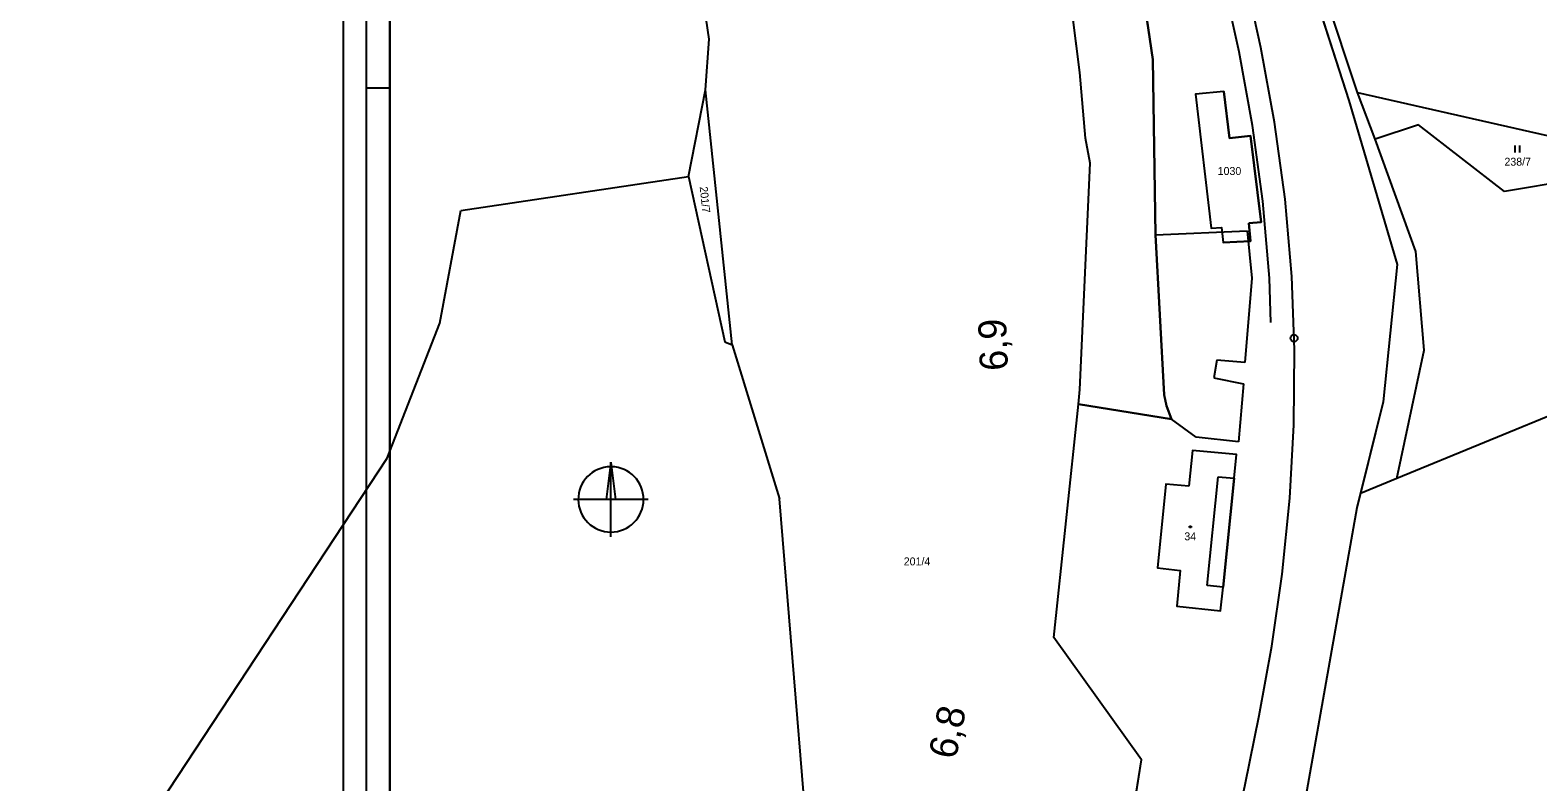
# Model space of a CAD drawing. Extents: x -866656 to -858817, y -1041816 to -1038653.
# Drawn here: x -864363.3 to -864040.4, y -1040809.9 to -1040648.8 of the extents above; entities that cross this region are included whole.
import ezdxf

# ---------------------------------------------------------------- set-up
doc = ezdxf.new("R2010")
doc.units = 0
for name, color, linetype in [('SZDC', 7, 'Continuous'), ('tisk ramy', 7, 'Continuous'), ('Vrstva 1', 7, 'Continuous'), ('Vrstva 2', 7, 'Continuous'), ('Vrstva 53', 7, 'Continuous'), ('Vrstva 7', 7, 'Continuous')]:
    doc.layers.add(name, color=color, linetype=linetype)

msp = doc.modelspace()

# ---------------------------------------------------------------- linework, layer by layer
at = {"layer": 'SZDC'}
for points in [[(-864163.47, -1040355.8), (-864153.11, -1040402.25), (-864151.77, -1040408.23), (-864141.64, -1040383.5), (-864136.16, -1040395.65), (-864121.34, -1040428.57), (-864124.99, -1040437.14), (-864137.01, -1040440.86), (-864126.47, -1040480.6), (-864126.25, -1040482.63), (-864122.51, -1040516.53), (-864121.02, -1040529.98), (-864108.77, -1040562.65), (-864093.71, -1040623.91), (-864080.87, -1040663.9), (-864070.5, -1040699.08), (-864073.5, -1040728.47), (-864078.36, -1040748.13), (-864079.13, -1040751.24), (-864090.67, -1040816.12)], [(-864137.28, -1040882.02), (-864125.28, -1040805.21), (-864144.05, -1040778.98), (-864138.75, -1040728.98), (-864118.82, -1040732.22), (-864119.89, -1040729.32), (-864120.42, -1040726.97), (-864122.3, -1040692.73), (-864122.82, -1040655.1), (-864130.24, -1040604.77)]]:
    msp.add_lwpolyline(points, dxfattribs=at)
for points in [[(-864102.25, -1040690.17), (-864099.63, -1040689.99), (-864101.89, -1040671.5), (-864106.42, -1040671.95), (-864107.6, -1040662), (-864113.68, -1040662.55), (-864110.32, -1040691.28), (-864108.15, -1040691.1), (-864107.78, -1040694.36), (-864101.89, -1040694.07)], [(-864115.12, -1040746.58), (-864120.02, -1040746.11), (-864121.83, -1040764.1), (-864116.95, -1040764.63), (-864117.71, -1040772.29), (-864108.31, -1040773.32), (-864107.79, -1040768.23), (-864105.43, -1040744.86), (-864104.93, -1040739.79), (-864114.31, -1040738.89)]]:
    msp.add_lwpolyline(points, close=True, dxfattribs=at)
at = {"layer": 'tisk ramy'}
msp.add_line((-864286.23, -1040661.26), (-864291.22, -1040661.26), dxfattribs=at)
for points in [[(-863999.23, -1041291.26), (-863999.23, -1040031.27), (-864296.22, -1040031.27), (-864296.22, -1041291.26)], [(-864291.22, -1041286.26), (-864291.22, -1040036.27), (-864004.23, -1040036.27), (-864004.23, -1041286.26)], [(-864009.22, -1041281.26), (-864009.22, -1040246.26), (-864286.22, -1040246.26), (-864286.22, -1041281.26)], [(-864286.22, -1041281.26), (-864286.22, -1040246.26), (-864009.22, -1040246.26), (-864009.22, -1041281.26)]]:
    msp.add_lwpolyline(points, close=True, dxfattribs=at)
at = {"layer": 'Vrstva 1'}
for p, q in [((-864130.24, -1040604.77), (-864122.82, -1040655.1)), ((-864093.71, -1040623.91), (-864080.87, -1040663.9)), ((-864217.87, -1040650.75), (-864220.9, -1040629.98)), ((-864138.47, -1040657.89), (-864140.94, -1040638.06)), ((-864078.98, -1040662.19), (-864087.52, -1040636.57)), ((-864218.64, -1040661.64), (-864217.87, -1040650.75)), ((-864122.82, -1040655.1), (-864122.3, -1040692.73)), ((-864137.29, -1040671.97), (-864138.47, -1040657.89)), ((-864222.26, -1040680.2), (-864218.64, -1040661.64)), ((-864212.92, -1040716.27), (-864218.64, -1040661.64)), ((-864107.6, -1040662), (-864113.68, -1040662.55)), ((-864113.68, -1040662.55), (-864110.32, -1040691.28)), ((-864107.6, -1040662), (-864106.42, -1040671.95)), ((-864080.87, -1040663.9), (-864070.5, -1040699.08)), ((-864078.98, -1040662.19), (-864011.96, -1040677.46)), ((-864075.25, -1040672.21), (-864078.98, -1040662.19)), ((-864065.91, -1040669.11), (-864075.25, -1040672.21)), ((-864047.56, -1040683.4), (-864065.91, -1040669.11)), ((-864136.27, -1040677.33), (-864137.29, -1040671.97)), ((-864106.42, -1040671.95), (-864101.89, -1040671.5)), ((-864101.89, -1040671.5), (-864099.63, -1040689.99)), ((-864066.53, -1040696.26), (-864075.25, -1040672.21)), ((-864045.3, -1040673.53), (-864045.3, -1040675.03)), ((-864044.3, -1040673.53), (-864044.3, -1040675.03)), ((-864138.47, -1040725.87), (-864136.27, -1040677.33)), ((-864011.96, -1040677.46), (-864047.56, -1040683.4)), ((-864271.06, -1040687.48), (-864222.26, -1040680.2)), ((-864222.26, -1040680.2), (-864214.49, -1040715.64)), ((-864275.5, -1040711.64), (-864271.06, -1040687.48)), ((-864122.3, -1040692.73), (-864120.42, -1040726.97)), ((-864110.32, -1040691.28), (-864108.15, -1040691.1)), ((-864108.15, -1040691.1), (-864107.78, -1040694.36)), ((-864099.63, -1040689.99), (-864102.25, -1040690.17)), ((-864102.25, -1040690.17), (-864101.89, -1040694.07)), ((-864101.89, -1040694.07), (-864107.78, -1040694.36)), ((-864064.76, -1040717.39), (-864066.53, -1040696.26)), ((-864070.5, -1040699.08), (-864073.5, -1040728.47)), ((-864286.84, -1040740.55), (-864275.5, -1040711.64)), ((-864214.49, -1040715.64), (-864212.92, -1040716.27)), ((-864212.92, -1040716.27), (-864202.79, -1040749.28)), ((-864070.57, -1040744.9), (-864064.76, -1040717.39)), ((-864014.38, -1040721.85), (-864070.57, -1040744.9)), ((-864138.75, -1040728.98), (-864138.47, -1040725.87)), ((-864120.42, -1040726.97), (-864119.89, -1040729.32)), ((-864073.5, -1040728.47), (-864079.13, -1040751.24)), ((-864144.05, -1040778.98), (-864138.75, -1040728.98)), ((-864118.82, -1040732.22), (-864138.75, -1040728.98)), ((-864119.89, -1040729.32), (-864118.82, -1040732.22)), ((-864363.26, -1040856.85), (-864286.84, -1040740.55)), ((-864114.31, -1040738.89), (-864115.12, -1040746.58)), ((-864104.93, -1040739.79), (-864114.31, -1040738.89)), ((-864105.43, -1040744.86), (-864104.93, -1040739.79)), ((-864120.02, -1040746.11), (-864121.83, -1040764.1)), ((-864115.12, -1040746.58), (-864120.02, -1040746.11)), ((-864105.43, -1040744.86), (-864107.79, -1040768.23)), ((-864070.57, -1040744.9), (-864078.36, -1040748.13)), ((-864192.21, -1040878.63), (-864202.79, -1040749.28)), ((-864079.13, -1040751.24), (-864090.67, -1040816.12)), ((-864114.95, -1040755.14), (-864114.65, -1040755.14)), ((-864114.95, -1040755.44), (-864114.95, -1040755.14)), ((-864114.65, -1040755.44), (-864114.95, -1040755.44)), ((-864114.65, -1040755.14), (-864114.65, -1040755.44)), ((-864121.83, -1040764.1), (-864116.95, -1040764.63)), ((-864116.95, -1040764.63), (-864117.71, -1040772.29)), ((-864108.31, -1040773.32), (-864107.79, -1040768.23)), ((-864117.71, -1040772.29), (-864108.31, -1040773.32)), ((-864125.28, -1040805.21), (-864144.05, -1040778.98)), ((-864137.28, -1040882.02), (-864125.28, -1040805.21))]:
    msp.add_line(p, q, dxfattribs=at)
for points in [[(-864097.54, -1040711.48), (-864097.87, -1040701.96), (-864099.26, -1040685.52), (-864101.52, -1040669.26), (-864104.38, -1040653.46), (-864107.83, -1040637.59), (-864111.43, -1040621.89), (-864114.88, -1040606.2), (-864115.97, -1040599.59), (-864117.84, -1040584.06), (-864118.34, -1040579.59)], [(-864106.24, -1040825.76), (-864103.09, -1040810.5), (-864100.1, -1040795.72), (-864097.36, -1040780.89), (-864095.11, -1040765.45), (-864093.48, -1040749.15), (-864092.63, -1040733.44), (-864092.48, -1040717.35), (-864093.09, -1040701.61), (-864094.53, -1040685.03), (-864096.79, -1040668.55), (-864099.73, -1040652.55), (-864103.2, -1040636.58), (-864106.87, -1040620.67), (-864110.47, -1040605.21), (-864116.49, -1040579.33)]]:
    msp.add_lwpolyline(points, dxfattribs=at)
at = {"layer": 'Vrstva 2'}
for p, q in [((-864122.3, -1040692.73), (-864102.65, -1040691.84)), ((-864102.65, -1040691.84), (-864101.61, -1040701.98)), ((-864101.61, -1040701.98), (-864103.15, -1040720.09)), ((-864109.12, -1040719.58), (-864109.8, -1040723.33)), ((-864103.15, -1040720.09), (-864109.12, -1040719.58)), ((-864109.8, -1040723.33), (-864103.4, -1040724.67)), ((-864103.4, -1040724.67), (-864104.47, -1040737.04)), ((-864113.55, -1040736.05), (-864118.82, -1040732.22)), ((-864104.47, -1040737.04), (-864113.55, -1040736.05)), ((-864238.89, -1040741.4), (-864239.89, -1040749.4)), ((-864238.89, -1040757.4), (-864238.89, -1040741.4)), ((-864111.22, -1040767.88), (-864108.86, -1040744.56)), ((-864108.86, -1040744.56), (-864105.43, -1040744.86)), ((-864230.89, -1040749.4), (-864246.89, -1040749.4)), ((-864107.79, -1040768.23), (-864111.22, -1040767.88))]:
    msp.add_line(p, q, dxfattribs=at)
msp.add_lwpolyline([(-864238.89, -1040741.4), (-864237.89, -1040749.4), (-864238.89, -1040749.4)], close=True, dxfattribs=at)
msp.add_arc((-864238.89, -1040749.4), 7, 91.0243, 88.9757, dxfattribs=at)
at = {"layer": 'Vrstva 53'}
for points in [[(-864163.47, -1040355.8), (-864153.11, -1040402.25), (-864151.77, -1040408.24), (-864141.64, -1040383.5), (-864136.16, -1040395.65), (-864121.34, -1040428.57), (-864124.99, -1040437.14), (-864137.01, -1040440.86), (-864126.47, -1040480.6), (-864126.25, -1040482.63), (-864122.51, -1040516.53), (-864121.02, -1040529.98), (-864108.77, -1040562.65), (-864093.71, -1040623.91), (-864080.87, -1040663.9), (-864070.5, -1040699.09), (-864073.5, -1040728.47), (-864078.36, -1040748.13), (-864079.13, -1040751.24), (-864090.67, -1040816.12), (-864108.73, -1040902.46), (-864114.59, -1040901.24), (-864124.2, -1040948.66)], [(-864138.75, -1040728.98), (-864138.47, -1040725.87), (-864136.27, -1040677.33), (-864137.29, -1040671.97), (-864138.47, -1040657.89), (-864140.94, -1040638.06), (-864141.38, -1040635.65), (-864151.49, -1040580.44), (-864163.71, -1040536.33), (-864169.06, -1040517.01), (-864150.41, -1040517.55)], [(-864151.94, -1040958.11), (-864146.26, -1040929.78), (-864137.28, -1040882.02), (-864125.28, -1040805.21), (-864144.05, -1040778.98), (-864138.75, -1040728.98)]]:
    msp.add_lwpolyline(points, dxfattribs=at)
at = {"layer": 'Vrstva 7'}
msp.add_circle((-864092.58, -1040714.85), 0.75, dxfattribs=at)

# ---------------------------------------------------------------- texts
at = {"layer": 'Vrstva 1'}
for s, p in [('238/7', (-864047.54, -1040677.88)), ('1030', (-864108.95, -1040679.87)), ('34', (-864116.09, -1040758.17)), ('201/4', (-864176.18, -1040763.54))]:
    msp.add_text(s, height=1.7, dxfattribs=at).set_placement(p)
msp.add_text('201/7', height=1.7, rotation=275.9805, dxfattribs=at).set_placement((-864219.88, -1040682.43))
at = {"layer": 'Vrstva 7'}
for s, rotation, p in [('6,9', 92.2261, (-864153.85, -1040721.72)), ('6,8', 78.3438, (-864165.04, -1040805.3))]:
    msp.add_text(s, height=6, rotation=rotation, dxfattribs=at).set_placement(p)

doc.saveas('drawing.dxf')
